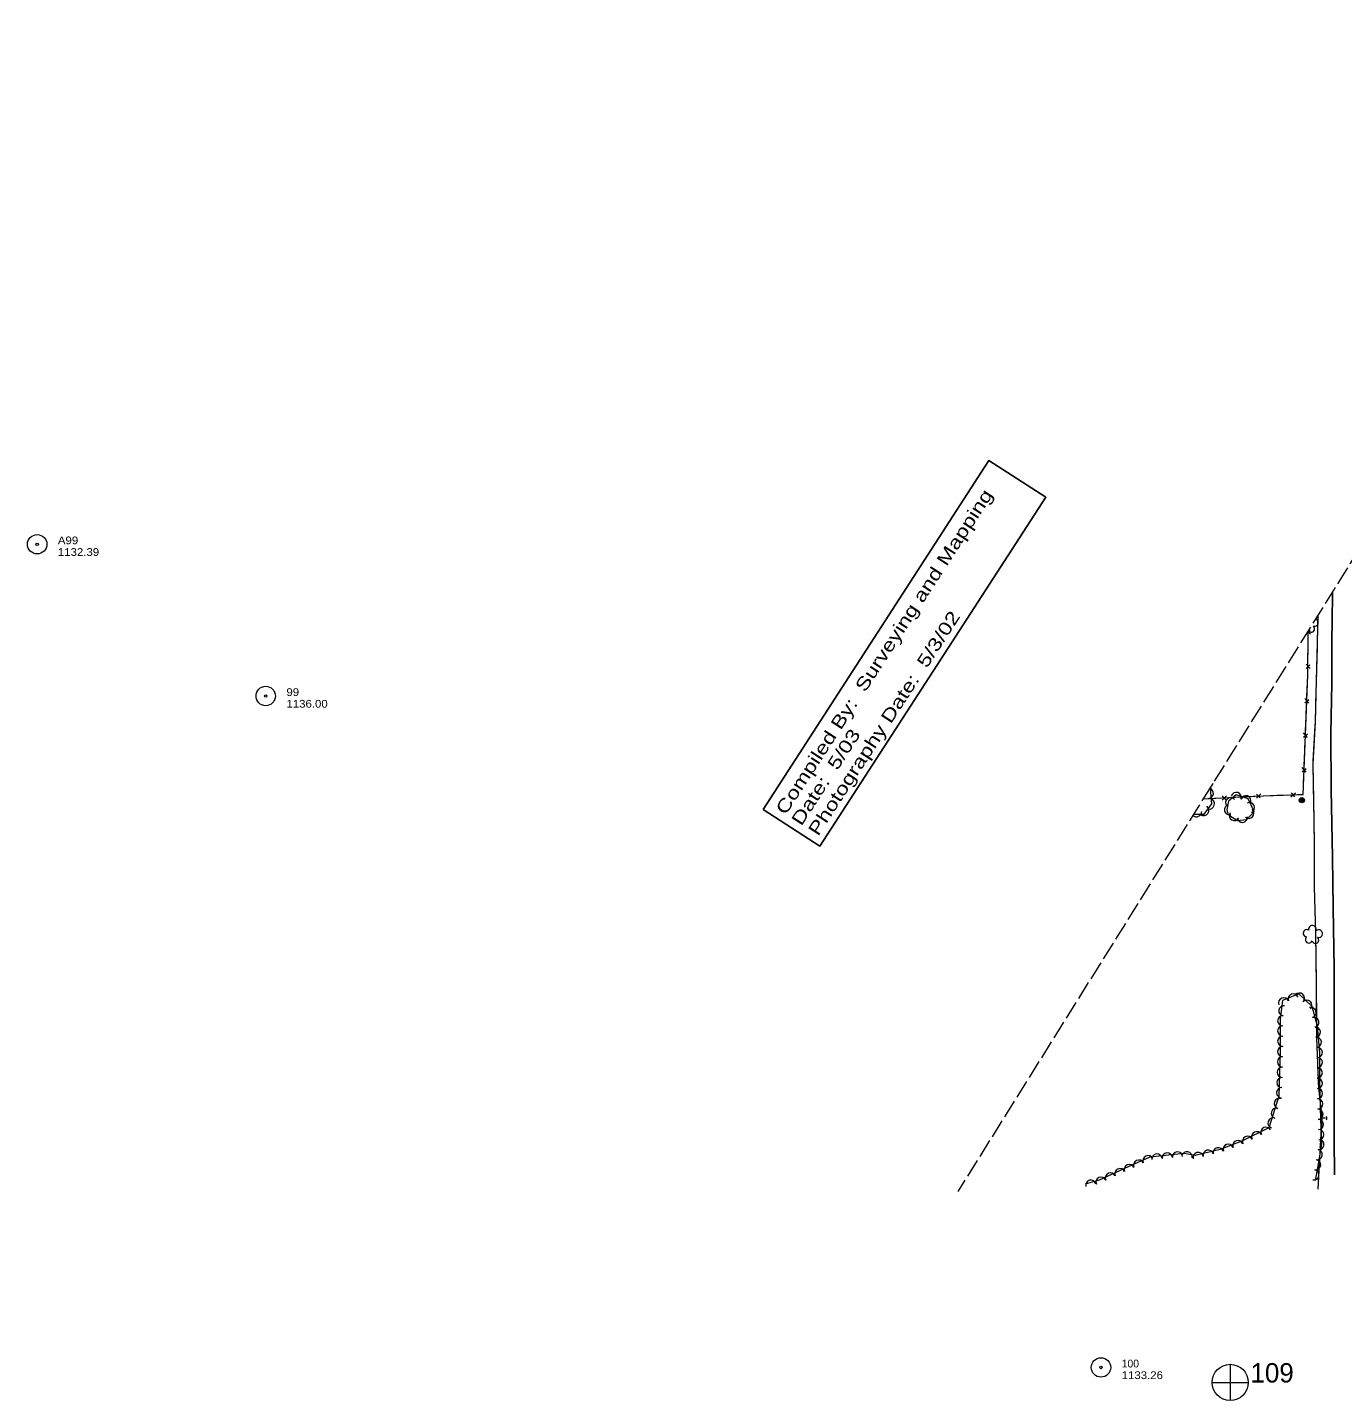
# Model space of a CAD drawing. Extents: x 296677 to 299172, y 46050 to 48373.
# Drawn here: x 296677 to 297694, y 46740 to 47801 of the extents above; entities that cross this region are included whole.
import ezdxf

# ---------------------------------------------------------------- set-up
doc = ezdxf.new("R2010")
doc.units = 0
doc.header["$LTSCALE"] = 2.4
doc.linetypes.add('LONG_DASHED', pattern=[7.5, 6, -1.5])
for name, color, linetype, lineweight in [('10', 7, 'Continuous', 25), ('11', 7, 'Continuous', 25), ('14', 7, 'Continuous', 13), ('15', 7, 'Continuous', 13), ('18', 7, 'Continuous', 13), ('19', 7, 'Continuous', 13), ('4', 7, 'Continuous', 13), ('6', 7, 'Continuous', 13)]:
    doc.layers.add(name, color=color, linetype=linetype, lineweight=lineweight)

msp = doc.modelspace()

# ---------------------------------------------------------------- linework, layer by layer
at = {"layer": '10'}
msp.add_lwpolyline([(297245.887, 47196.873), (297289.868, 47168.417), (297464.402, 47438.186), (297420.42, 47466.641)], close=True, dxfattribs=at)
at = {"layer": '11'}
msp.add_lwpolyline([(297687.551, 46914.245), (297687.226, 46941.879), (297687.202, 46982.714), (297687.248, 47030.779), (297687.227, 47074.336), (297686.486, 47120.419), (297685.876, 47159.928), (297685.022, 47211.874), (297684.773, 47255.607), (297685.458, 47294.401), (297685.37, 47326.187), (297686.017, 47362.018), (297686.004, 47365.035)], dxfattribs=at)
at = {"layer": '14'}
for centre, radius in [((297662.295, 47203.948), 2.018), ((297662.282, 47203.953), 1.518), ((297662.319, 47203.936), 1.008), ((297662.313, 47203.945), 0.502)]:
    msp.add_circle(centre, radius, dxfattribs=at)
at = {"layer": '15'}
for p, q in [((297665.773, 47332.496), (297668.833, 47335.144)), ((297668.872, 47332.304), (297666.958, 47334.542)), ((297667.108, 47321.68), (297667.197, 47331.21)), ((297667.007, 47310.845), (297667.108, 47321.68)), ((297668.623, 47305.64), (297665.556, 47309.226)), ((297665.524, 47305.831), (297668.584, 47308.479)), ((297666.254, 47284.192), (297666.687, 47295.019)), ((297664.619, 47279.227), (297667.758, 47281.78)), ((297667.71, 47278.94), (297664.755, 47282.619)), ((297665.622, 47268.375), (297666.003, 47277.897)), ((297665.19, 47257.548), (297665.622, 47268.375)), ((297666.646, 47252.296), (297663.69, 47255.974)), ((297663.555, 47252.582), (297666.694, 47255.135)), ((297664.558, 47241.73), (297664.938, 47251.253)), ((297664.126, 47230.903), (297664.558, 47241.73)), ((297662.49, 47225.937), (297665.63, 47228.49)), ((297665.582, 47225.651), (297662.626, 47229.33)), ((297663.494, 47215.086), (297663.874, 47224.608)), ((297586.005, 47204.934), (297589.945, 47205.158)), ((297589.945, 47205.158), (297599.46, 47205.698)), ((297600.649, 47207.203), (297603.493, 47204.325)), ((297600.663, 47204.099), (297604.039, 47207.396)), ((297605.75, 47206.055), (297616.568, 47206.669)), ((297627.251, 47205.556), (297630.7, 47208.777)), ((297627.307, 47208.66), (297630.086, 47205.719)), ((297632.38, 47207.398), (297643.21, 47207.769)), ((297643.21, 47207.769), (297652.734, 47208.096)), ((297653.901, 47206.471), (297657.35, 47209.691)), ((297653.957, 47209.574), (297656.736, 47206.633))]:
    msp.add_line(p, q, dxfattribs=at)
for points in [[(297586.005, 47204.934), (297624.843, 47207.139), (297663.229, 47208.456), (297666.912, 47300.66), (297667.232, 47334.981)], [(297666.687, 47295.019), (297666.912, 47300.66), (297666.948, 47304.545)], [(297659.031, 47208.312), (297663.229, 47208.456), (297663.494, 47215.086)], [(297616.568, 47206.669), (297624.843, 47207.139), (297626.084, 47207.182)]]:
    msp.add_lwpolyline(points, dxfattribs=at)
msp.add_arc((297680.061, 46958.001), 1.665, 310.36587, 56.60544, dxfattribs=at)
at = {"layer": '18'}
for points in [[(297578.623, 47193.116), (297586.917, 47193.1), (297592.856, 47201.103), (297591.597, 47213.199), (297591.626, 47213.934)], [(297672.8, 46910.003), (297674.71, 46919.85), (297675.829, 46927.421), (297677.717, 46938.385), (297676.882, 46957.259), (297676.274, 46986.264), (297676.318, 47008.694), (297674.428, 47029.234), (297670.243, 47044.539), (297659.895, 47054.194), (297647.444, 47049.229), (297645.47, 47034.61), (297645.468, 47009.998), (297644.646, 46975.134), (297636.736, 46950.676), (297616.545, 46940.603), (297599.16, 46933.91), (297579.851, 46929.268), (297571.417, 46930.752), (297544.715, 46928.125), (297528.17, 46920.398), (297505.612, 46910.245), (297494.836, 46907.204)]]:
    msp.add_lwpolyline(points, dxfattribs=at)
msp.add_lwpolyline([(297612.541, 47188.224), (297619.768, 47189.01), (297625.393, 47195.176), (297620.911, 47205.023), (297611.672, 47208.212), (297605.59, 47203.325), (297604.265, 47196.539), (297605.042, 47193.393), (297606.359, 47192.034)], close=True, dxfattribs=at)
for centre, radius, start, end in [((297672.062, 47341.358), 2.975, 251.66742, 71.98182), ((297669.602, 47336.413), 2.611, 209.36792, 54.30526), ((297589.633, 47217.857), 4.103, 304.72566, 351.29669), ((297589.837, 47209.368), 4.103, 275.94984, 70.69974), ((297590.686, 47201.208), 4.103, 275.94984, 95.93452), ((297607.26, 47202.01), 3.958, 38.79019, 218.77486), ((297611.555, 47206.061), 3.958, 340.96467, 160.94934), ((297619.036, 47203.479), 3.958, 340.96467, 160.94934), ((297580.807, 47195.259), 4.103, 227.95186, 359.88461), ((297586.438, 47196.058), 4.103, 233.42867, 53.41335), ((297606.401, 47196.528), 3.958, 103.88095, 283.86563), ((297610.259, 47192.064), 3.958, 148.36191, 328.34659), ((297621.34, 47193.807), 3.958, 227.63469, 47.61937), ((297621.779, 47198.115), 3.958, 294.48098, 114.46566), ((297616.252, 47190.711), 3.958, 186.21469, 6.19936), ((297666.127, 47101.1), 2.777, 56.98749, 264.76048), ((297667.795, 47096.321), 2.783, 133.66451, 334.67555), ((297670.509, 47104.211), 2.974, 334.0166, 195.25048), ((297672.816, 47095.867), 2.611, 196.37265, 54.30526), ((297675.276, 47100.812), 2.975, 251.66742, 134.64069), ((297655.671, 47050.268), 3.979, 21.74795, 201.73263), ((297660.36, 47050.912), 3.979, 316.99187, 136.97655), ((297648.28, 47047.32), 3.979, 21.74795, 201.73263), ((297648.452, 47041.133), 3.979, 82.31754, 262.30222), ((297666.178, 47045.483), 3.979, 316.99187, 136.97655), ((297669.379, 47039.802), 3.979, 285.30079, 105.28546), ((297647.553, 47033.516), 3.979, 90.00301, 269.98768), ((297671.478, 47032.127), 3.979, 285.30079, 105.28546), ((297647.552, 47025.559), 3.979, 90.00301, 269.98768), ((297672.756, 47024.673), 3.979, 275.26496, 95.24964), ((297647.542, 47009.596), 3.979, 88.65703, 268.64171), ((297647.551, 47017.602), 3.979, 90.00301, 269.98768), ((297673.485, 47016.749), 3.979, 275.26496, 95.24964), ((297674.215, 47008.825), 3.979, 275.26496, 95.24964), ((297647.354, 47001.641), 3.979, 88.65703, 268.64171), ((297674.22, 47001.064), 3.979, 269.89527, 89.87994), ((297647.167, 46993.686), 3.979, 88.65703, 268.64171), ((297674.205, 46993.107), 3.979, 269.89527, 89.87994), ((297646.791, 46977.775), 3.979, 88.65703, 268.64171), ((297646.979, 46985.73), 3.979, 88.65703, 268.64171), ((297674.215, 46985.102), 3.979, 271.20851, 91.19319), ((297674.382, 46977.147), 3.979, 271.20851, 91.19319), ((297645.007, 46969.483), 3.979, 72.08586, 252.07053), ((297674.549, 46969.191), 3.979, 271.20851, 91.19319), ((297642.559, 46961.911), 3.979, 72.08586, 252.07053), ((297674.716, 46961.236), 3.979, 271.20851, 91.19319), ((297634.594, 46947.28), 3.979, 26.52161, 206.50629), ((297640.11, 46954.34), 3.979, 72.08586, 252.07053), ((297674.975, 46953.235), 3.979, 272.54082, 92.5255), ((297675.327, 46945.285), 3.979, 272.54082, 92.5255), ((297605.444, 46934.097), 3.979, 21.06372, 201.0484), ((297612.87, 46936.956), 3.979, 21.06372, 201.0484), ((297620.353, 46940.176), 3.979, 26.52161, 206.50629), ((297627.474, 46943.728), 3.979, 26.52161, 206.50629), ((297675.502, 46937.794), 3.979, 260.23716, 80.22183), ((297543.355, 46925.192), 3.979, 25.04161, 205.02629), ((297550.377, 46926.589), 3.979, 5.62646, 185.61114), ((297558.296, 46927.368), 3.979, 5.62646, 185.61114), ((297566.215, 46928.148), 3.979, 5.62646, 185.61114), ((297573.543, 46928.263), 3.979, 350.02836, 170.01304), ((297582.203, 46927.692), 3.979, 13.52539, 193.51007), ((297589.94, 46929.552), 3.979, 13.52539, 193.51007), ((297597.677, 46931.412), 3.979, 13.52539, 193.51007), ((297674.152, 46929.952), 3.979, 260.23716, 80.22183), ((297521.653, 46915.181), 3.979, 24.23942, 204.2241), ((297528.909, 46918.447), 3.979, 24.23942, 204.2241), ((297536.146, 46921.824), 3.979, 25.04161, 205.02629), ((297671.513, 46914.306), 3.979, 259.03044, 79.01512), ((297672.928, 46922.04), 3.979, 261.60017, 81.58484), ((297499.23, 46906.28), 3.979, 15.76679, 195.75147), ((297507.14, 46908.649), 3.979, 24.23942, 204.2241), ((297514.396, 46911.915), 3.979, 24.23942, 204.2241)]:
    msp.add_arc(centre, radius, start, end, dxfattribs=at)
at = {"layer": '19'}
for p, q in [((297674.745, 47337.195), (297674.988, 47347.398)), ((297673.744, 47298.392), (297673.794, 47300.286)), ((297673.895, 47304.072), (297673.945, 47305.966)), ((297673.584, 47292.712), (297673.639, 47294.605)), ((297671.156, 47234.027), (297672.61, 47261.468)), ((297671.101, 47228.348), (297671.066, 47230.241)), ((297671.207, 47222.666), (297671.172, 47224.56)), ((297671.314, 47216.985), (297671.278, 47218.879)), ((297672.128, 47152.547), (297672.125, 47154.443)), ((297672.137, 47146.859), (297672.134, 47148.755)), ((297672.146, 47141.171), (297672.143, 47143.067)), ((297673.468, 47076.717), (297673.448, 47078.613)), ((297673.527, 47071.029), (297673.507, 47072.925)), ((297673.585, 47065.34), (297673.566, 47067.236)), ((297674.638, 47000.887), (297674.565, 47002.781)), ((297674.859, 46995.203), (297674.786, 46997.097)), ((297675.08, 46989.518), (297675.007, 46991.413)), ((297676.125, 46927.038), (297676.2, 46928.475)), ((297676.352, 46931.347), (297676.428, 46932.783)), ((297676.579, 46935.655), (297676.655, 46937.092)), ((297674.874, 46903.342), (297675.973, 46924.166))]:
    msp.add_line(p, q, dxfattribs=at)
for points in [[(297678.134, 46958.404), (297675.392, 46981.508), (297673.895, 47019.998), (297673.634, 47060.581), (297673.216, 47101.21), (297672.153, 47136.878), (297672.1, 47170.644), (297671.554, 47204.122), (297671.037, 47231.774), (297672.753, 47264.17), (297673.683, 47296.113), (297674.481, 47326.087), (297674.988, 47347.399)], [(297674.046, 47309.753), (297674.481, 47326.087), (297674.745, 47337.195)], [(297672.61, 47261.468), (297672.753, 47264.17), (297673.474, 47288.924)], [(297671.854, 47185.722), (297671.554, 47204.122), (297671.384, 47213.197)], [(297672.119, 47158.235), (297672.1, 47170.644), (297671.854, 47185.722)], [(297672.957, 47109.895), (297672.153, 47136.878), (297672.152, 47137.379)], [(297673.409, 47082.405), (297673.216, 47101.21), (297672.957, 47109.895)], [(297673.805, 47034.054), (297673.634, 47060.581), (297673.624, 47061.548)], [(297674.417, 47006.571), (297673.895, 47019.998), (297673.805, 47034.054)], [(297678.134, 46958.404), (297675.392, 46981.508), (297675.228, 46985.729)], [(297674.874, 46903.342), (297676.885, 46941.447), (297678.134, 46958.404), (297680.485, 46958.307)], [(297676.807, 46939.964), (297676.885, 46941.447), (297678.134, 46958.404), (297680.485, 46958.307)]]:
    msp.add_lwpolyline(points, dxfattribs=at)
at = {"layer": '4'}
for p, q in [((297606.9, 46767.883), (297606.835, 46740.029)), ((297592.991, 46753.853), (297620.896, 46753.84))]:
    msp.add_line(p, q, dxfattribs=at)
at = {"layer": '4', "linetype": 'LONG_DASHED'}
msp.add_lwpolyline([(298026.893, 47801.312), (297840.58, 47612.516), (297396.47, 46901.483)], dxfattribs=at)
at = {"layer": '4'}
msp.add_circle((297606.952, 46753.861), 14, dxfattribs=at)
at = {"layer": '6'}
for centre, radius in [((296684.935, 47401.791), 7.5), ((296684.935, 47401.791), 0.96), ((296861.559, 47284.495), 7.5), ((296861.559, 47284.495), 0.96), ((297507.068, 46765.452), 7.5), ((297507.068, 46765.452), 0.96)]:
    msp.add_circle(centre, radius, dxfattribs=at)

# ---------------------------------------------------------------- texts
at = {"layer": '10', "width": 1.3}
for s, p in [('Compiled By:  Surveying and Mapping', (297263.393, 47191.888)), ('Photography Date:  5/3/02  ', (297288.497, 47175.646)), ('Date:  5/03    ', (297275.511, 47183.468))]:
    msp.add_text(s, height=10, rotation=57.098, dxfattribs=at).set_placement(p)
at = {"layer": '4'}
msp.add_text('109', height=15, dxfattribs=at).set_placement((297622.604, 46753.791))
at = {"layer": '6', "width": 1.1}
for s, p in [('A99', (296700.935, 47401.791)), ('1132.39', (296700.935, 47392.791)), ('99', (296877.559, 47284.495)), ('1136.00', (296877.559, 47275.495)), ('1133.26', (297523.068, 46756.452))]:
    msp.add_text(s, height=6, dxfattribs=at).set_placement(p)
at = {"layer": '6'}
msp.add_text('100', height=6, dxfattribs=at).set_placement((297523.068, 46765.452))

doc.saveas('drawing.dxf')
